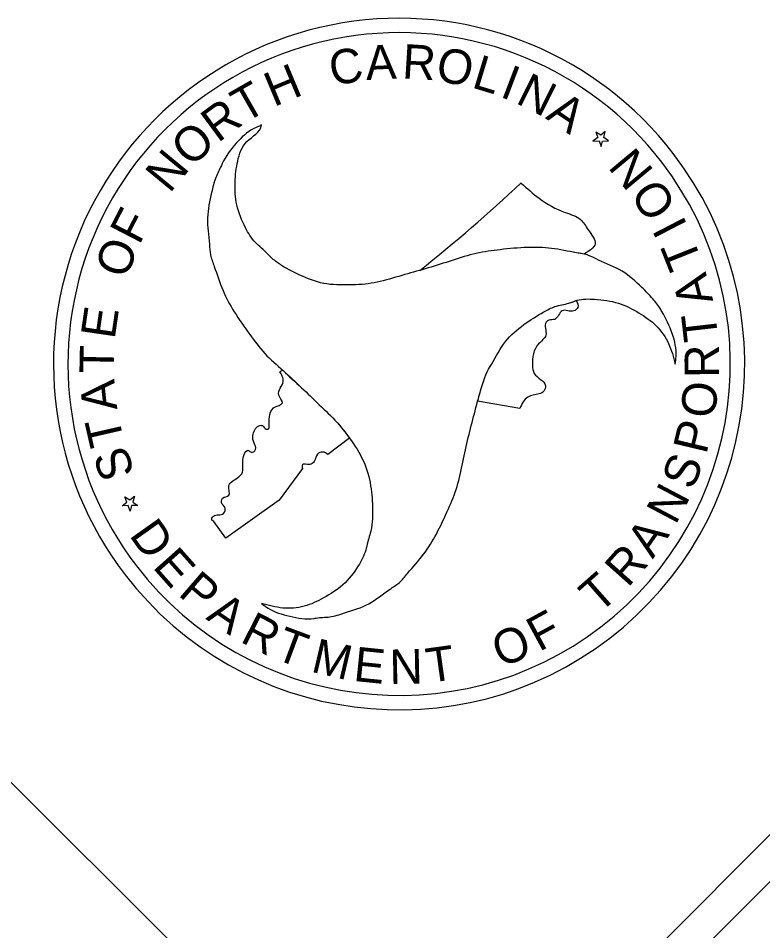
# Model space of a CAD drawing. Extents: x 1481763 to 1495577, y 493394 to 506245.
# Drawn here: x 1490155.2 to 1490495.9, y 498919.6 to 499336.9 of the extents above; entities that cross this region are included whole.
import ezdxf

# ---------------------------------------------------------------- set-up
doc = ezdxf.new("R2010")
doc.units = 0
doc.layers.add('Sheet Title CELL', color=7, linetype='Continuous')

msp = doc.modelspace()

# ---------------------------------------------------------------- linework, layer by layer
at = {"layer": 'Sheet Title CELL'}
for p, q in [((1490266.43, 499288.32), (1490266.41, 499287.88)), ((1490266.43, 499288.32), (1490266.41, 499287.88)), ((1490421.77, 499283.42), (1490419.48, 499284.85)), ((1490419.48, 499284.85), (1490420.36, 499282.33)), ((1490423.83, 499285.12), (1490421.77, 499283.42)), ((1490423.11, 499282.44), (1490423.83, 499285.12)), ((1490420.36, 499282.33), (1490418.2, 499280.68)), ((1490418.2, 499280.68), (1490420.96, 499280.78)), ((1490420.96, 499280.78), (1490421.92, 499278.22)), ((1490421.92, 499278.22), (1490422.63, 499280.77)), ((1490422.63, 499280.77), (1490425.34, 499280.84)), ((1490425.34, 499280.84), (1490423.11, 499282.44)), ((1490454.85, 499275.14), (1490454.85, 499275.14)), ((1490339.03, 499221.61), (1490339.03, 499221.61)), ((1490317.02, 498823), (1489976.9, 499161.7)), ((1490384.72, 499158.47), (1490365.43, 499161.8)), ((1490365.43, 499161.8), (1490365.43, 499161.8)), ((1490306.9, 499144.96), (1490296.89, 499137.44)), ((1490285.21, 499130.95), (1490274.65, 499116.45)), ((1490204.88, 499115.63), (1490203.93, 499118.09)), ((1490203.93, 499118.09), (1490206.21, 499116.66)), ((1490206.21, 499116.66), (1490208.37, 499118.31)), ((1490208.37, 499118.31), (1490207.59, 499115.64)), ((1490202.68, 499113.94), (1490204.88, 499115.63)), ((1490205.43, 499113.98), (1490202.68, 499113.94)), ((1490206.4, 499111.42), (1490205.43, 499113.98)), ((1490207.07, 499114), (1490206.4, 499111.42)), ((1490209.85, 499114.07), (1490207.07, 499114)), ((1490207.59, 499115.64), (1490209.85, 499114.07)), ((1490274.65, 499116.45), (1490250.18, 499099.07)), ((1490250.18, 499099.07), (1490244.64, 499106.81))]:
    msp.add_line(p, q, dxfattribs=at)
for points in [[(1487576.27, 496007), (1490709.29, 499153.08)], [(1490359.45, 498823.09), (1490688.05, 499153.06)]]:
    msp.add_lwpolyline(points, dxfattribs=at)
for centre, radius, start, end in [((1490329.48, 499178.76), 158.15, 37.5398, 217.5398), ((1490329.48, 499178.76), 151.56, 37.5398, 217.5398), ((1490329.48, 499178.76), 158.15, 217.5398, 37.5398), ((1490329.48, 499178.76), 151.56, 217.5398, 37.5398), ((1489818.16, 499872.75), 833.83, 308.6573, 312.86332), ((1489818.16, 499872.75), 833.83, 303.21825, 303.31785)]:
    msp.add_arc(centre, radius, start, end, dxfattribs=at)
for points in [[(1490266.41, 499287.88), (1490263.01, 499286.46), (1490254.95, 499279.72), (1490248.56, 499270.5), (1490248.13, 499269.52), (1490245.6, 499264.03), (1490243.68, 499257.23), (1490241.82, 499245.58), (1490242.7, 499233.66), (1490243.21, 499228.68), (1490244.89, 499223.34), (1490248.9, 499212.36), (1490254.02, 499202.69), (1490261.14, 499192.27), (1490268.03, 499183.61), (1490276.37, 499175.76), (1490284.87, 499167.93), (1490292.91, 499160.16), (1490301.07, 499152.07), (1490308, 499143.14), (1490308.56, 499142.33), (1490314.3, 499131.55), (1490316.86, 499120.22), (1490317.28, 499109.37), (1490316.83, 499103.88), (1490315.14, 499097.38), (1490314.22, 499093.65), (1490310.76, 499086.39), (1490303.72, 499077.78), (1490294.94, 499071.81), (1490286.05, 499067.99), (1490276.28, 499067.17), (1490266.49, 499069.22)], [(1490455.86, 499178.74), (1490456.25, 499182.23), (1490454.51, 499192.65), (1490449.72, 499202.81), (1490449.18, 499203.75), (1490445.57, 499208.6), (1490440.62, 499213.73), (1490431.54, 499221.23), (1490420.74, 499226.29), (1490416.21, 499228.42), (1490410.65, 499229.65), (1490399.18, 499231.65), (1490388.27, 499232.08), (1490375.7, 499231.05), (1490364.78, 499229.34), (1490353.7, 499226.14), (1490342.75, 499222.7), (1490332.09, 499219.65), (1490320.82, 499216.54), (1490309.72, 499215.05), (1490308.72, 499215.05), (1490296.4, 499215.4), (1490285.32, 499218.88), (1490275.71, 499223.85), (1490271.35, 499227.07), (1490266.52, 499231.81), (1490263.62, 499234.43), (1490259.21, 499241.09), (1490255.2, 499251.54), (1490254.43, 499262.01), (1490255.62, 499271.61), (1490259.83, 499280.52), (1490266.41, 499287.88), (1490266.43, 499288.32)], [(1490385.38, 499261.54), (1490393.59, 499254.55), (1490405.54, 499248.07), (1490412.51, 499244.85), (1490416, 499240.15), (1490419.18, 499233.78), (1490414.26, 499229.11)], [(1490414.25, 499229.05), (1490410.65, 499229.65), (1490399.18, 499231.65), (1490388.27, 499232.08), (1490375.7, 499231.05), (1490364.78, 499229.34), (1490353.7, 499226.14), (1490342.75, 499222.7), (1490339.03, 499221.61)], [(1490266.49, 499069.22), (1490269.55, 499067.08), (1490279.4, 499063.41), (1490290.57, 499062.42), (1490291.56, 499062.59), (1490297.72, 499063.12), (1490304.5, 499064.91), (1490315.61, 499069.07), (1490325.32, 499075.82), (1490329.44, 499078.69), (1490333.38, 499083.02), (1490340.69, 499091.83), (1490346.53, 499100.99), (1490352.02, 499112.47), (1490355.99, 499122.68), (1490358.7, 499133.93), (1490361.15, 499145.21), (1490363.94, 499156.04), (1490366.93, 499167.15), (1490371.11, 499177.63), (1490371.71, 499178.62), (1490378.15, 499189.01), (1490386.59, 499196.8), (1490395.64, 499202.57), (1490400.78, 499205.04), (1490407.2, 499206.6), (1490410.98, 499207.91), (1490418.93, 499208.41), (1490429.86, 499206.58), (1490439.36, 499202.06), (1490447.18, 499196.19), (1490452.78, 499188.13), (1490455.86, 499178.74)], [(1490365.43, 499161.8), (1490366.93, 499167.15), (1490371.11, 499177.63), (1490371.71, 499178.62), (1490378.15, 499189.01), (1490386.59, 499196.8), (1490395.64, 499202.57), (1490400.78, 499205.04), (1490407.2, 499206.6), (1490410.73, 499207.78)], [(1490410.72, 499207.71), (1490411.25, 499204.63), (1490409.47, 499203.03), (1490404.14, 499203.13), (1490400.71, 499199.2), (1490398.03, 499198.85), (1490396.77, 499197.94), (1490396.66, 499192), (1490393.33, 499188.03), (1490390.51, 499178.23), (1490391.32, 499174.42), (1490396.43, 499168.77), (1490395.74, 499166.35), (1490393.58, 499165.16), (1490388.37, 499163.64), (1490384.72, 499158.47)], [(1490244.64, 499106.81), (1490243.83, 499107.32), (1490244.47, 499109.11), (1490249.12, 499110.37), (1490249.73, 499113.26), (1490248.48, 499114.73), (1490248.72, 499117.34), (1490251.51, 499118.71), (1490251.56, 499123.19), (1490253.2, 499125.21), (1490257.44, 499128.47), (1490258.57, 499137.38), (1490260.46, 499139.3), (1490262.01, 499138.37), (1490263.51, 499139.11), (1490262.47, 499144.93), (1490262.57, 499145.95), (1490265.31, 499150.54), (1490266.92, 499150.59), (1490268.64, 499148.96), (1490269.49, 499149.02), (1490270.07, 499150.95), (1490270.11, 499154.52), (1490272.06, 499158.68), (1490276.08, 499161.06), (1490274.4, 499164.56), (1490276.48, 499170.77), (1490276.03, 499173.2), (1490274.88, 499175.16)], [(1490276.16, 499175.96), (1490276.37, 499175.76), (1490284.87, 499167.93), (1490292.91, 499160.16), (1490301.07, 499152.07), (1490306.86, 499144.93)], [(1490296.89, 499137.44), (1490294.52, 499138.52), (1490292.16, 499137.59), (1490290.61, 499134.22), (1490288.56, 499132.82), (1490285.2, 499132.72), (1490285.21, 499130.95)]]:
    msp.add_spline(points, degree=3, dxfattribs=at)

# ---------------------------------------------------------------- texts
for s, height, rotation, p in [('C', 15.72, 10.3388, (1490298.99, 499305.88)), ('A', 15.76, 2.8418, (1490314.49, 499308.63)), ('R', 15.75, 356.4778, (1490330.64, 499309.46)), ('O', 15.8, 349.3582, (1490345.69, 499308.49)), ('L', 15.73, 343.1245, (1490362.2, 499305.39)), ('H', 15.75, 22.6811, (1490272.12, 499296.23)), ('I', 15.79, 339.1352, (1490375.15, 499301.16)), ('N', 15.76, 333.4351, (1490382.3, 499298.31)), ('T', 15.81, 29.7659, (1490258.66, 499288.67)), ('R', 15.77, 36.4155, (1490246.52, 499279.69)), ('A', 15.77, 326.0031, (1490396.09, 499291.29)), ('O', 15.81, 43.0254, (1490234.33, 499268.32)), ('N', 15.77, 50.5235, (1490224.46, 499256.47)), ('N', 15.77, 129.7479, (1490446.54, 499267.1)), ('O', 15.71, 122.4999, (1490456.92, 499251.14)), ('F', 15.8, 62.6105, (1490210.53, 499232.82)), ('I', 15.81, 117.3642, (1490461.67, 499242.19)), ('O', 15.79, 69.7573, (1490204.67, 499217.21)), ('T', 15.75, 111.7143, (1490468.33, 499225.68)), ('A', 15.8, 104.6299, (1490473.26, 499207.65)), ('E', 15.72, 81.6967, (1490199.27, 499189.77)), ('T', 15.72, 96.5429, (1490475.58, 499189.93)), ('T', 15.73, 88.8123, (1490198.89, 499174.34)), ('R', 15.8, 90.4431, (1490475.94, 499172.46)), ('A', 15.82, 95.8675, (1490200.54, 499158.11)), ('O', 15.8, 83.254, (1490473.82, 499153.52)), ('T', 15.8, 102.9199, (1490203.79, 499143.05)), ('P', 15.76, 76.562, (1490470.03, 499137.07)), ('S', 15.75, 109.296, (1490208.71, 499128.86)), ('S', 15.7, 69.3701, (1490463.98, 499120.71)), ('N', 15.72, 62.1597, (1490455.94, 499104.78)), ('D', 15.77, 305.3928, (1490205.67, 499100.51)), ('A', 15.72, 55.128, (1490445.53, 499089.33)), ('E', 15.7, 311.6806, (1490216.29, 499085.85)), ('R', 15.78, 48.3749, (1490434.14, 499076.15)), ('P', 15.77, 319.213, (1490227.91, 499073.27)), ('T', 15.72, 41.4183, (1490420.87, 499064.18)), ('A', 15.75, 325.8056, (1490240.68, 499062.27)), ('R', 15.77, 332.8743, (1490256.24, 499051.94)), ('F', 15.75, 28.5091, (1490393.58, 499046.99)), ('T', 15.75, 339.5248, (1490271.8, 499044.15)), ('O', 15.76, 21.3438, (1490375.93, 499039.81)), ('M', 15.73, 346.7598, (1490288.66, 499038.13)), ('E', 15.73, 354.2266, (1490308.26, 499033.86)), ('N', 15.8, 1.1981, (1490325.21, 499032.34)), ('T', 15.75, 8.0401, (1490343, 499032.89))]:
    msp.add_text(s, height=height, rotation=rotation, dxfattribs=at).set_placement(p)

doc.saveas('drawing.dxf')
